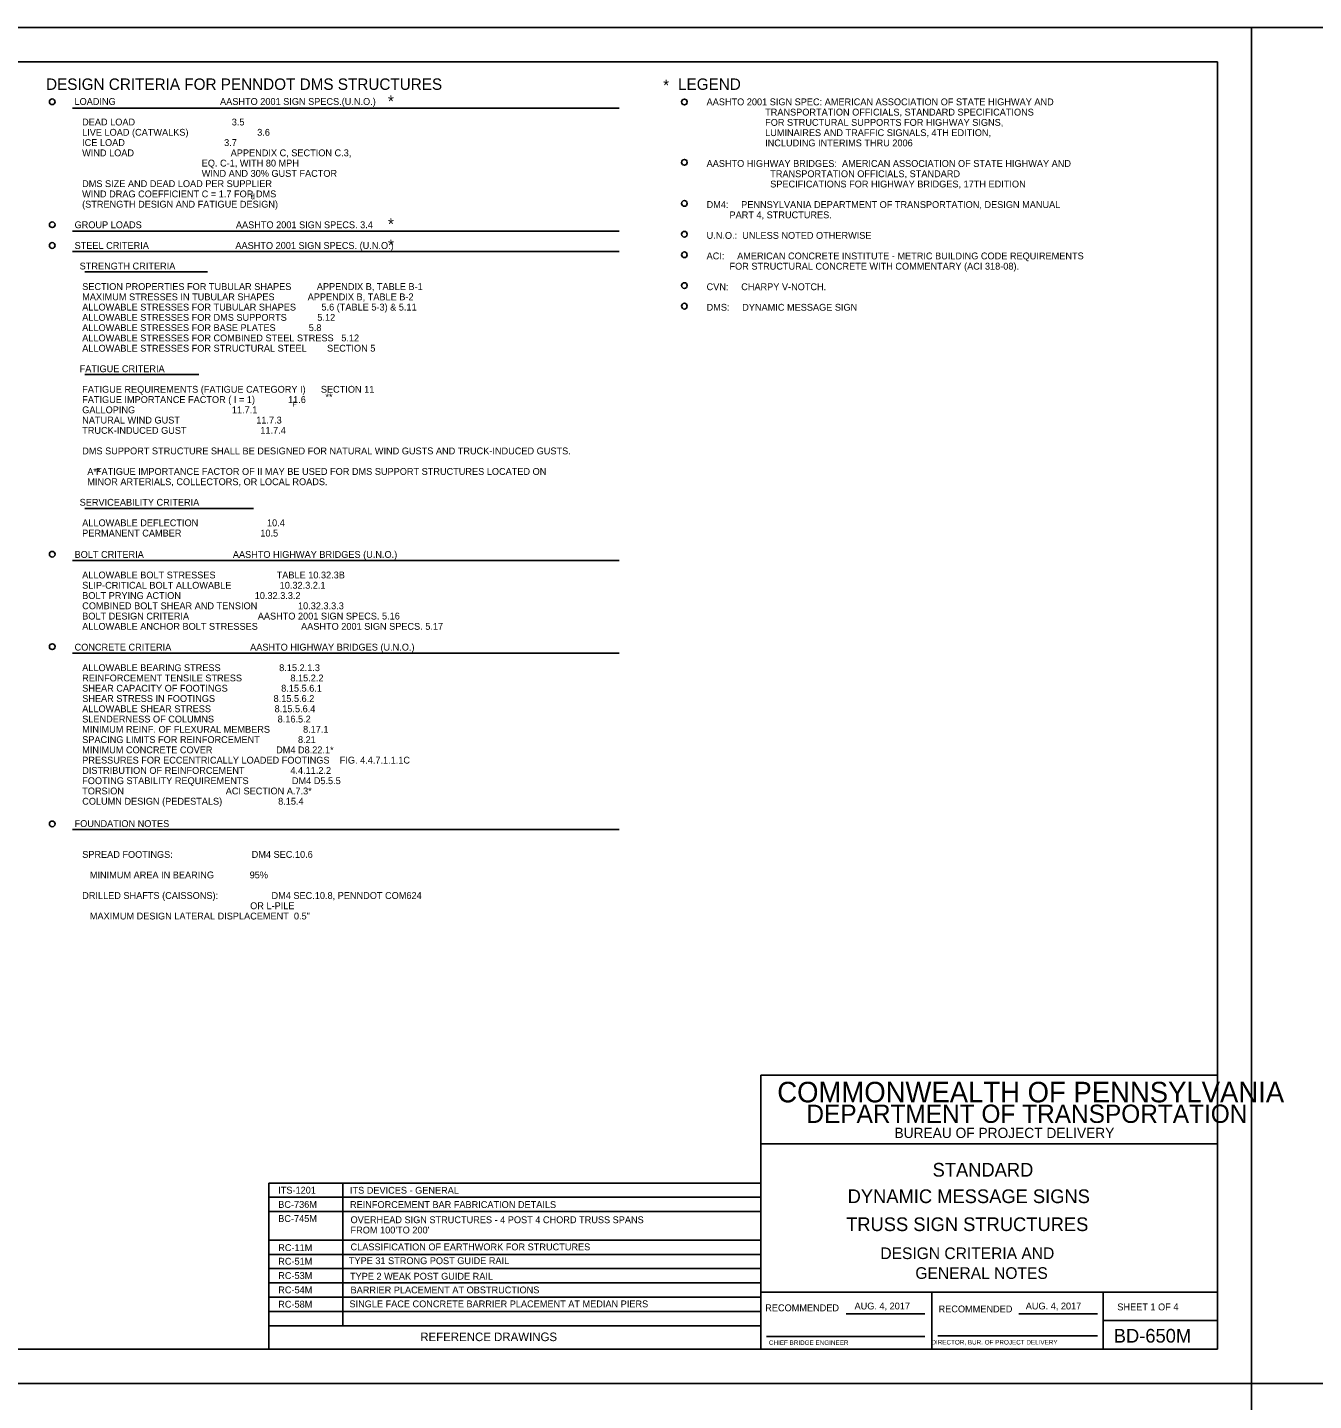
# Model space of a CAD drawing. Extents: x 3831399 to 3833095, y 499014 to 500202.
# Drawn here: x 3831704 to 3832267, y 499601 to 500202 of the extents above; entities that cross this region are included whole.
import ezdxf

# ---------------------------------------------------------------- set-up
doc = ezdxf.new("R2010")
doc.units = 0
for name, color, linetype in [('10', 7, 'Continuous'), ('13', 7, 'Continuous'), ('2', 7, 'Continuous'), ('DIM TXT', 7, 'Continuous'), ('PLT-BNDY', 7, 'Continuous')]:
    doc.layers.add(name, color=color, linetype=linetype)

msp = doc.modelspace()

# ---------------------------------------------------------------- linework, layer by layer
at = {"layer": '10'}
for p, q in [((3831723.81, 500166.68), (3831963.14, 500166.68)), ((3831723.81, 500112.82), (3831963.14, 500112.82)), ((3831723.81, 500103.82), (3831963.14, 500103.82)), ((3831729.14, 500094.92), (3831782.93, 500094.92)), ((3831729.14, 500049.97), (3831779.13, 500049.97)), ((3831729.14, 499991.36), (3831803.01, 499991.36)), ((3831723.81, 499968.48), (3831963.14, 499968.48)), ((3831723.81, 499927.98), (3831963.14, 499927.98)), ((3831723.81, 499850.66), (3831963.14, 499850.66))]:
    msp.add_line(p, q, dxfattribs=at)
at = {"layer": '13'}
for p, q in [((3831809.69, 499695.82), (3832025.16, 499695.82)), ((3831809.69, 499623.03), (3831809.69, 499695.82)), ((3831842.16, 499633.32), (3831842.16, 499695.82)), ((3831809.69, 499689.57), (3832025.16, 499689.57)), ((3831809.69, 499683.32), (3832025.16, 499683.32)), ((3831809.69, 499670.82), (3832025.16, 499670.82)), ((3831809.69, 499664.57), (3832025.16, 499664.57)), ((3831809.69, 499658.32), (3832025.16, 499658.32)), ((3831809.69, 499652.07), (3832025.16, 499652.07)), ((3831809.69, 499645.82), (3832025.16, 499645.82)), ((3831809.69, 499639.57), (3832025.16, 499639.57)), ((3831809.69, 499633.32), (3832025.16, 499633.32))]:
    msp.add_line(p, q, dxfattribs=at)
at = {"layer": '2'}
for p, q in [((3831439.16, 500187.03), (3832225.16, 500187.03)), ((3832225.16, 500187.03), (3832225.16, 499623.03)), ((3832225.16, 499743.03), (3832025.16, 499743.03)), ((3832025.16, 499743.03), (3832025.16, 499623.03)), ((3832225.16, 499713.03), (3832025.16, 499713.03)), ((3832225.16, 499648.03), (3832025.16, 499648.03)), ((3832100.16, 499623.03), (3832100.16, 499648.03)), ((3832175.16, 499648.03), (3832175.16, 499623.03)), ((3832062.62, 499638.53), (3832097.03, 499638.53)), ((3832138.24, 499638.53), (3832172.65, 499638.53)), ((3832175.16, 499635.53), (3832225.16, 499635.53)), ((3832027.66, 499628.53), (3832097.03, 499628.53)), ((3832102.79, 499628.9), (3832172.65, 499628.9)), ((3832225.16, 499623.03), (3831439.16, 499623.03)), ((3832025.16, 499623.03), (3832225.16, 499623.03))]:
    msp.add_line(p, q, dxfattribs=at)
at = {"layer": 'DIM TXT'}
for centre in [(3831714.88, 500169.47), (3831714.88, 500169.47), (3831991.72, 500169.38), (3831991.72, 500142.94), (3831991.72, 500124.94), (3831714.88, 500115.63), (3831991.72, 500111.44), (3831714.88, 500106.52), (3831991.72, 500102.44), (3831991.72, 500088.94), (3831991.72, 500079.94), (3831714.88, 499971.26), (3831714.88, 499930.78), (3831714.88, 499853.14)]:
    msp.add_circle(centre, 1.25, dxfattribs=at)
at = {"layer": 'PLT-BNDY'}
for points in [[(3831399.16, 500202.03), (3832240.16, 500202.03), (3832240.16, 499608.03), (3831399.16, 499608.03)], [(3832240.16, 500202.03), (3833081.16, 500202.03), (3833081.16, 499608.03), (3832240.16, 499608.03)], [(3831399.16, 499608.03), (3832240.16, 499608.03), (3832240.16, 499014.03), (3831399.16, 499014.03)], [(3832240.16, 499608.03), (3833081.16, 499608.03), (3833081.16, 499014.03), (3832240.16, 499014.03)]]:
    msp.add_lwpolyline(points, close=True, dxfattribs=at)

# ---------------------------------------------------------------- texts
at = {"layer": '10'}
for s, height, p in [('STANDARD ', 6, (3832100.43, 499698.62)), ('ITS-1201', 3, (3831813.85, 499691.18)), ('ITS DEVICES - GENERAL', 3.0001, (3831845.27, 499691.13)), ('DYNAMIC MESSAGE SIGNS', 6, (3832063.23, 499687.02)), ('BC-736M', 3, (3831813.85, 499684.93)), ('REINFORCEMENT BAR FABRICATION DETAILS', 3.0001, (3831845.27, 499684.88)), ('BC-745M', 3, (3831813.85, 499678.76)), ('OVERHEAD SIGN STRUCTURES - 4 POST 4 CHORD TRUSS SPANS', 3.0001, (3831845.52, 499678.22)), ('TRUSS SIGN STRUCTURES', 6, (3832062.56, 499674.76)), ("FROM 100'TO 200'", 3.0001, (3831845.52, 499673.72)), ('RC-11M', 3, (3831813.85, 499666.02)), ('CLASSIFICATION OF EARTHWORK FOR STRUCTURES', 3.0001, (3831845.52, 499666.34)), ('DESIGN CRITERIA AND', 5.1, (3832077.57, 499662.5)), ('RC-51M', 3, (3831813.85, 499660.05)), ('TYPE 31 STRONG POST GUIDE RAIL', 3.0001, (3831844.78, 499660.29)), ('RC-53M', 3, (3831813.85, 499653.78)), ('TYPE 2 WEAK POST GUIDE RAIL', 3.0001, (3831845.27, 499653.49)), ('GENERAL NOTES', 5.1, (3832092.89, 499653.83)), ('RC-54M', 3, (3831813.85, 499647.51)), ('BARRIER PLACEMENT AT OBSTRUCTIONS', 3.0001, (3831845.52, 499647.48)), ('RC-58M', 3, (3831813.85, 499641.23)), ('SINGLE FACE CONCRETE BARRIER PLACEMENT AT MEDIAN PIERS', 3.0001, (3831845.03, 499641.37)), ('REFERENCE DRAWINGS', 3.7501, (3831876.06, 499626.56))]:
    msp.add_text(s, height=height, dxfattribs=at).set_placement(p)
at = {"layer": '2'}
for s, height, p in [('COMMONWEALTH OF PENNSYLVANIA', 9, (3832032.41, 499731.15)), ('DEPARTMENT OF TRANSPORTATION', 8.0002, (3832045.16, 499722.15)), ('BUREAU OF PROJECT DELIVERY', 4.5, (3832083.75, 499715.53)), ('AUG. 4, 2017', 3, (3832066.24, 499640.44)), ('AUG. 4, 2017', 3, (3832141.24, 499640.44)), ('SHEET 1 OF 4', 3, (3832181.36, 499640.04)), ('BD-650M', 6, (3832179.79, 499625.9)), ('CHIEF BRIDGE ENGINEER', 2.0002, (3832028.75, 499624.9)), ('   DIRECTOR, BUR. OF PROJECT DELIVERY', 2.0002, (3832097.63, 499625.08))]:
    msp.add_text(s, height=height, dxfattribs=at).set_placement(p)
for p in [(3832027.14, 499639.64), (3832103.07, 499639.15)]:
    msp.add_text('RECOMMENDED', height=3, rotation=360, dxfattribs=at).set_placement(p)
at = {"layer": 'DIM TXT'}
for s, height, p in [('DESIGN CRITERIA FOR PENNDOT DMS STRUCTURES', 4.9999, (3831712.15, 500174.69)), ('*', 5, (3831982.43, 500174.17)), ('LEGEND', 5, (3831988.96, 500174.69)), ('*', 5, (3831861.91, 500167.23)), ('LOADING                                         AASHTO 2001 SIGN SPECS.(U.N.O.)', 2.9999, (3831724.61, 500168.1)), ('AASHTO 2001 SIGN SPEC: AMERICAN ASSOCIATION OF STATE HIGHWAY AND', 2.9999, (3832001.46, 500167.94)), ('                       TRANSPORTATION OFFICIALS, STANDARD SPECIFICATIONS', 2.9999, (3832001.46, 500163.44)), ('   DEAD LOAD                                      3.5 ', 2.9999, (3831724.61, 500159.1)), ('                       FOR STRUCTURAL SUPPORTS FOR HIGHWAY SIGNS,', 2.9999, (3832001.46, 500158.94)), ('   LIVE LOAD (CATWALKS)                           3.6', 2.9999, (3831724.61, 500154.6)), ('                       LUMINAIRES AND TRAFFIC SIGNALS, 4TH EDITION,', 2.9999, (3832001.46, 500154.44)), ('   WIND LOAD                                      APPENDIX C, SECTION C.3, ', 2.9999, (3831724.61, 500145.6)), ('   ICE LOAD                                       3.7', 2.9999, (3831724.61, 500150.1)), ('                       INCLUDING INTERIMS THRU 2006', 2.9999, (3832001.46, 500149.94)), ('                                                  EQ. C-1, WITH 80 MPH ', 2.9999, (3831724.61, 500141.1)), ('AASHTO HIGHWAY BRIDGES:  AMERICAN ASSOCIATION OF STATE HIGHWAY AND', 2.9999, (3832001.46, 500140.94)), ('                                                  WIND AND 30% GUST FACTOR', 2.9999, (3831724.61, 500136.6)), ('                         TRANSPORTATION OFFICIALS, STANDARD', 2.9999, (3832001.46, 500136.44)), ('   WIND DRAG COEFFICIENT C = 1.7 FOR DMS', 2.9999, (3831724.61, 500127.61)), ('   DMS SIZE AND DEAD LOAD PER SUPPLIER', 2.9999, (3831724.61, 500132.1)), ('d', 2.5, (3831801.8, 500126.78)), ('                         SPECIFICATIONS FOR HIGHWAY BRIDGES, 17TH EDITION', 2.9999, (3832001.46, 500131.94)), ('   (STRENGTH DESIGN AND FATIGUE DESIGN)', 2.9999, (3831724.61, 500123.11)), ('DM4:     PENNSYLVANIA DEPARTMENT OF TRANSPORTATION, DESIGN MANUAL', 2.9999, (3832001.46, 500122.94)), ('*', 5, (3831861.91, 500113.43)), ('         PART 4, STRUCTURES.', 2.9999, (3832001.46, 500118.44)), ('GROUP LOADS                                     AASHTO 2001 SIGN SPECS. 3.4', 2.9999, (3831724.65, 500114.08)), ('U.N.O.:  UNLESS NOTED OTHERWISE', 2.9999, (3832001.46, 500109.44)), ('STEEL CRITERIA                                  AASHTO 2001 SIGN SPECS. (U.N.O.)', 2.9999, (3831724.65, 500105.02)), ('*', 5, (3831861.91, 500104.14)), ('ACI:     AMERICAN CONCRETE INSTITUTE - METRIC BUILDING CODE REQUIREMENTS', 2.9999, (3832001.46, 500100.44)), ('  STRENGTH CRITERIA', 2.9999, (3831724.65, 500096.02)), ('         FOR STRUCTURAL CONCRETE WITH COMMENTARY (ACI 318-08).', 2.9999, (3832001.46, 500095.94)), ('   SECTION PROPERTIES FOR TUBULAR SHAPES          APPENDIX B, TABLE B-1', 2.9999, (3831724.65, 500087.02)), ('CVN:     CHARPY V-NOTCH.', 2.9999, (3832001.46, 500086.94)), ('   ALLOWABLE STRESSES FOR TUBULAR SHAPES          5.6 (TABLE 5-3) & 5.11', 2.9999, (3831724.65, 500078.02)), ('   MAXIMUM STRESSES IN TUBULAR SHAPES             APPENDIX B, TABLE B-2', 2.9999, (3831724.65, 500082.52)), ('   ALLOWABLE STRESSES FOR DMS SUPPORTS            5.12', 2.9999, (3831724.65, 500073.52)), ('DMS:     DYNAMIC MESSAGE SIGN', 2.9999, (3832001.46, 500077.94)), ('   ALLOWABLE STRESSES FOR BASE PLATES             5.8', 2.9999, (3831724.65, 500069.02)), ('   ALLOWABLE STRESSES FOR COMBINED STEEL STRESS   5.12', 2.9999, (3831724.65, 500064.52)), ('   ALLOWABLE STRESSES FOR STRUCTURAL STEEL        SECTION 5', 2.9999, (3831724.65, 500060.02)), ('  FATIGUE CRITERIA', 2.9999, (3831724.65, 500051.02)), ('   FATIGUE REQUIREMENTS (FATIGUE CATEGORY I)      SECTION 11', 2.9999, (3831724.65, 500042.02)), ('   FATIGUE IMPORTANCE FACTOR ( I = 1)             11.6', 2.9999, (3831724.65, 500037.52)), ('**', 3, (3831834.51, 500038.68)), ('   GALLOPING                                      11.7.1', 2.9999, (3831724.65, 500033.02)), ('F', 2.25, (3831820.08, 500035.84)), ('   TRUCK-INDUCED GUST                             11.7.4', 2.9999, (3831724.65, 500024.02)), ('   NATURAL WIND GUST                              11.7.3', 2.9999, (3831724.65, 500028.52)), ('   DMS SUPPORT STRUCTURE SHALL BE DESIGNED FOR NATURAL WIND GUSTS AND TRUCK-INDUCED GUSTS.', 2.9999, (3831724.65, 500015.02)), ('     A FATIGUE IMPORTANCE FACTOR OF II MAY BE USED FOR DMS SUPPORT STRUCTURES LOCATED ON', 2.9999, (3831724.65, 500006.02)), ('**', 3, (3831732.81, 500005.97)), ('     MINOR ARTERIALS, COLLECTORS, OR LOCAL ROADS.', 2.9999, (3831724.65, 500001.52)), ('  SERVICEABILITY CRITERIA', 2.9999, (3831724.65, 499992.52)), ('   ALLOWABLE DEFLECTION                           10.4', 2.9999, (3831724.65, 499983.52)), ('   PERMANENT CAMBER                               10.5', 2.9999, (3831724.65, 499979.02)), ('BOLT CRITERIA                                   AASHTO HIGHWAY BRIDGES (U.N.O.)', 2.9999, (3831724.65, 499969.67)), ('   ALLOWABLE BOLT STRESSES                        TABLE 10.32.3B', 2.9999, (3831724.65, 499960.67)), ('   SLIP-CRITICAL BOLT ALLOWABLE                   10.32.3.2.1', 2.9999, (3831724.65, 499956.17)), ('   COMBINED BOLT SHEAR AND TENSION                10.32.3.3.3', 2.9999, (3831724.65, 499947.17)), ('   BOLT PRYING ACTION                             10.32.3.3.2', 2.9999, (3831724.65, 499951.67)), ('   BOLT DESIGN CRITERIA                           AASHTO 2001 SIGN SPECS. 5.16', 2.9999, (3831724.65, 499942.67)), ('   ALLOWABLE ANCHOR BOLT STRESSES                 AASHTO 2001 SIGN SPECS. 5.17', 2.9999, (3831724.65, 499938.17)), ('CONCRETE CRITERIA                               AASHTO HIGHWAY BRIDGES (U.N.O.)', 2.9999, (3831724.65, 499929.06)), ('   ALLOWABLE BEARING STRESS                       8.15.2.1.3', 2.9999, (3831724.65, 499920.06)), ('   SHEAR CAPACITY OF FOOTINGS                     8.15.5.6.1', 2.9999, (3831724.65, 499911.06)), ('   REINFORCEMENT TENSILE STRESS                   8.15.2.2', 2.9999, (3831724.65, 499915.56)), ('   SHEAR STRESS IN FOOTINGS                       8.15.5.6.2', 2.9999, (3831724.65, 499906.56)), ('   ALLOWABLE SHEAR STRESS                         8.15.5.6.4', 2.9999, (3831724.65, 499902.06)), ('   SLENDERNESS OF COLUMNS                         8.16.5.2', 2.9999, (3831724.65, 499897.56)), ('   MINIMUM REINF. OF FLEXURAL MEMBERS             8.17.1', 2.9999, (3831724.65, 499893.06)), ('   SPACING LIMITS FOR REINFORCEMENT               8.21', 2.9999, (3831724.65, 499888.56)), ('   MINIMUM CONCRETE COVER                         DM4 D8.22.1*', 2.9999, (3831724.65, 499884.06)), ('   PRESSURES FOR ECCENTRICALLY LOADED FOOTINGS    FIG. 4.4.7.1.1.1C', 2.9999, (3831724.65, 499879.56)), ('   DISTRIBUTION OF REINFORCEMENT                  4.4.11.2.2', 2.9999, (3831724.65, 499875.06)), ('   FOOTING STABILITY REQUIREMENTS                 DM4 D5.5.5', 2.9999, (3831724.65, 499870.56)), ('   TORSION                                        ACI SECTION A.7.3*', 2.9999, (3831724.65, 499866.06)), ('   COLUMN DESIGN (PEDESTALS)                      8.15.4', 2.9999, (3831724.65, 499861.56)), ('FOUNDATION NOTES', 2.9999, (3831724.65, 499851.77)), ('   SPREAD FOOTINGS:                               DM4 SEC.10.6', 2.9999, (3831724.65, 499838.27)), ('      MINIMUM AREA IN BEARING              95%', 2.9999, (3831724.65, 499829.27)), ('   DRILLED SHAFTS (CAISSONS):                     DM4 SEC.10.8, PENNDOT COM624 ', 2.9999, (3831724.65, 499820.27)), ('                                                                     OR L-PILE', 2.9999, (3831724.65, 499815.77)), ('      MAXIMUM DESIGN LATERAL DISPLACEMENT  0.5"', 2.9999, (3831724.65, 499811.27))]:
    msp.add_text(s, height=height, dxfattribs=at).set_placement(p)

doc.saveas('drawing.dxf')
